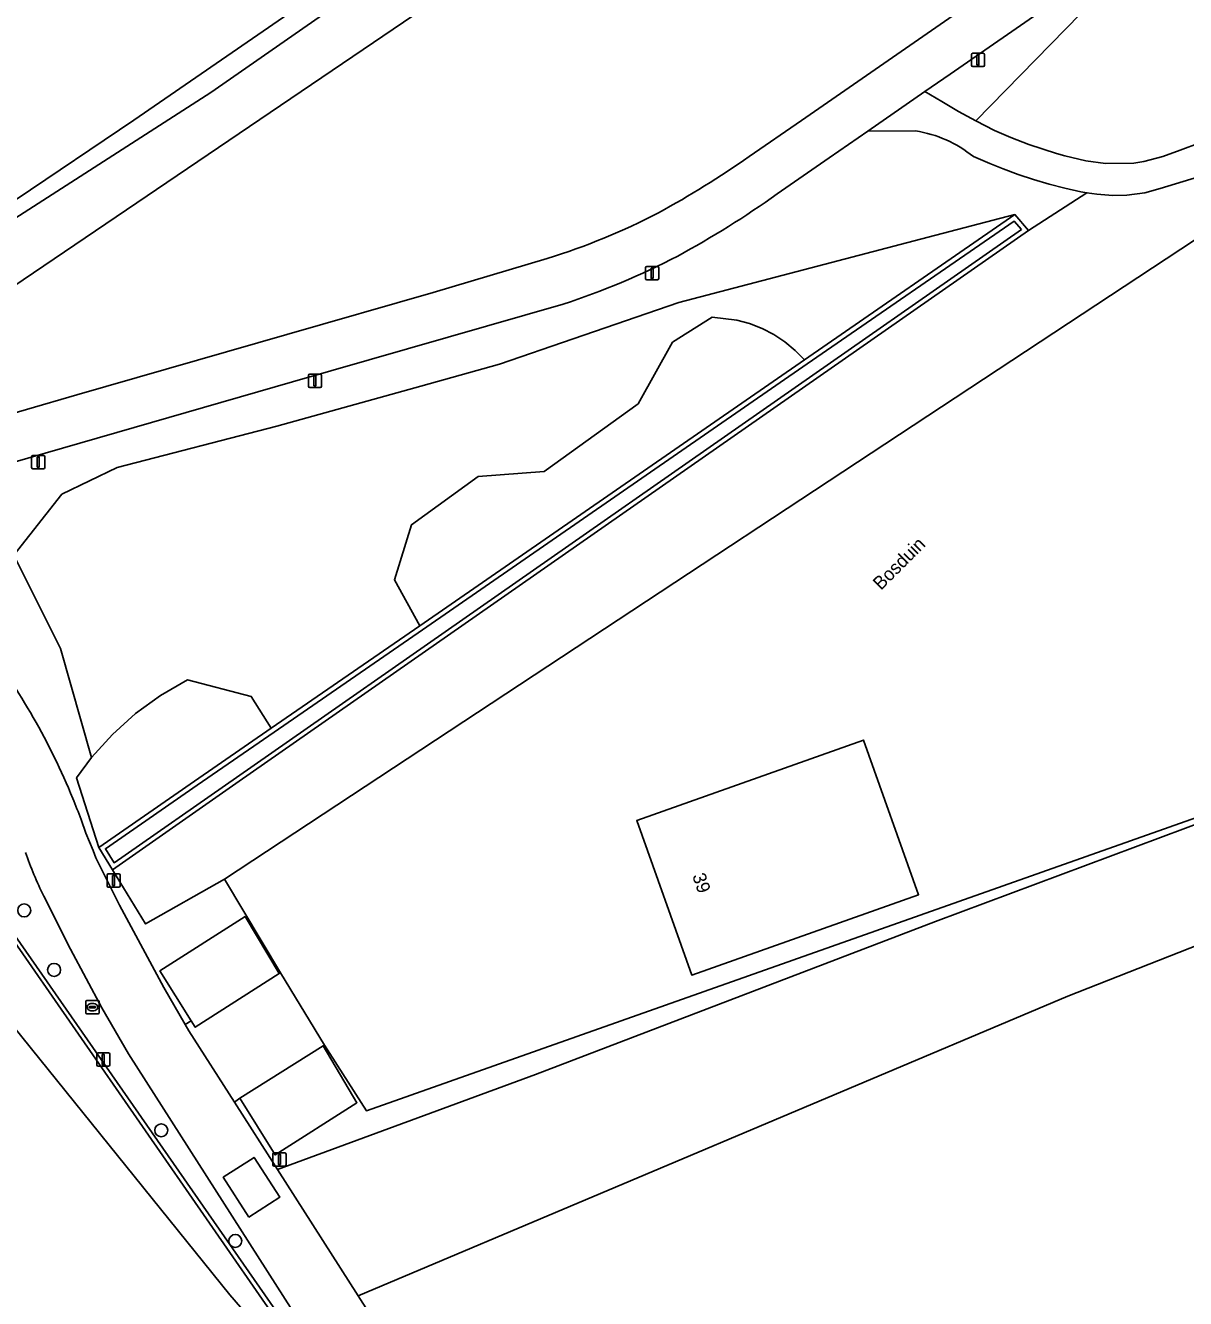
# Model space of a CAD drawing. Extents: x 156661 to 157576, y 383570 to 384425.
# Drawn here: x 157206.8 to 157294, y 383711.1 to 383806.8 of the extents above; entities that cross this region are included whole.
import ezdxf

# ---------------------------------------------------------------- set-up
doc = ezdxf.new("R2010")
doc.units = 0
for name, color, linetype in [('IMGEO_Berm_groen', 7, 'Continuous'), ('IMGEO_Boom', 7, 'Continuous'), ('IMGEO_Brandkraan', 7, 'Continuous'), ('IMGEO_Erf', 7, 'Continuous'), ('IMGEO_Fietspad_gesloten', 7, 'Continuous'), ('IMGEO_Gemengd_bos', 7, 'Continuous'), ('IMGEO_Groenvoorziening', 7, 'Continuous'), ('IMGEO_Hek', 7, 'Continuous'), ('IMGEO_Lichtmast', 7, 'Continuous'), ('IMGEO_Oever', 7, 'Continuous'), ('IMGEO_Openbare_ruimte_label', 7, 'Continuous'), ('IMGEO_Pand', 7, 'Continuous'), ('IMGEO_Pand_nummerreeks', 7, 'Continuous'), ('IMGEO_Parkeervlak_open', 7, 'Continuous'), ('IMGEO_Rijbaan_lokaal_halfverhard', 7, 'Continuous'), ('IMGEO_Rijbaan_lokaal_open', 7, 'Continuous'), ('IMGEO_Voetpad_open', 7, 'Continuous'), ('IMGEO_Waterloop', 7, 'Continuous')]:
    doc.layers.add(name, color=color, linetype=linetype)

msp = doc.modelspace()

# ---------------------------------------------------------------- linework, layer by layer
at = {"layer": 'IMGEO_Berm_groen'}
for points in [[(157198.145, 383748.914), (157205.551, 383738.59), (157225.711, 383709.501)], [(157229.992, 383702.365), (157230.186, 383702.14), (157237.396, 383693.8), (157214.571, 383729.509), (157212.581, 383732.98), (157210.224, 383737.387), (157208.207, 383741.37)]]:
    msp.add_lwpolyline(points, dxfattribs=at)
msp.add_arc((157234.02, 383754.094), 28.778, 199.14383, 206.23945, dxfattribs=at)
at = {"layer": 'IMGEO_Boom'}
for centre in [(157206.737, 383740.299), (157208.985, 383735.823), (157217.042, 383723.758), (157222.607, 383715.439)]:
    msp.add_circle(centre, 0.489, dxfattribs=at)
at = {"layer": 'IMGEO_Brandkraan'}
for p, q in [((157211.369, 383732.595), (157211.369, 383733.447)), ((157211.444, 383733.521), (157212.296, 383733.521)), ((157211.857, 383733.301), (157211.882, 383733.301)), ((157212.37, 383733.447), (157212.37, 383732.595)), ((157212.296, 383732.521), (157211.444, 383732.521)), ((157211.628, 383733.015), (157211.628, 383733.027)), ((157212.066, 383732.978), (157211.668, 383732.978)), ((157211.671, 383733.064), (157212.069, 383733.064)), ((157211.88, 383732.741), (157211.855, 383732.741)), ((157212.112, 383733.027), (157212.112, 383733.015))]:
    msp.add_line(p, q, dxfattribs=at)
for points in [[(157211.369, 383732.595), (157211.369, 383733.447)], [(157211.444, 383733.521), (157212.296, 383733.521)], [(157212.37, 383733.447), (157212.37, 383732.595)], [(157212.296, 383732.521), (157211.444, 383732.521)]]:
    msp.add_lwpolyline(points, dxfattribs=at)
for centre, radius, start, end in [((157211.446, 383733.445), 0.0765, 91.55205, 178.44795), ((157211.446, 383733.445), 0.0765, 91.55205, 178.44795), ((157212.294, 383733.445), 0.0765, 1.55205, 88.44795), ((157212.294, 383733.445), 0.0765, 1.55205, 88.44795), ((157211.446, 383732.597), 0.0765, 181.55205, 268.44795), ((157211.446, 383732.597), 0.0765, 181.55205, 268.44795), ((157211.668, 383733.024), 0.0403, 85.87752, 175.75265), ((157211.665, 383733.014), 0.0366, 178.93798, 274.71019), ((157212.069, 383733.021), 0.043, 264.86636, 352.45326), ((157212.073, 383733.026), 0.0386, 1.73085, 96.63898), ((157212.294, 383732.597), 0.0765, 271.55205, 358.44795), ((157212.294, 383732.597), 0.0765, 271.55205, 358.44795)]:
    msp.add_arc(centre, radius, start, end, dxfattribs=at)
for centre, major_axis, ratio, start_param, end_param in [((157211.856, 383733.021), (-0.387, 0.002), 0.722429, 4.712389, 7.853982), ((157211.881, 383733.021), (-0.39, 0.002), 0.717154, 1.570796, 4.712389)]:
    msp.add_ellipse(centre, major_axis=major_axis, ratio=ratio, start_param=start_param, end_param=end_param, dxfattribs=at)
at = {"layer": 'IMGEO_Erf'}
for points in [[(157324.866, 383757.87), (157348.567, 383774.345), (157335.149, 383794.067), (157314.431, 383779.837), (157312.332, 383778.396), (157311.319, 383777.7), (157300.001, 383794.175), (157221.789, 383742.655), (157226.005, 383735.606), (157229.305, 383730.173), (157232.472, 383725.228)], [(157269.845, 383753.105), (157273.982, 383741.469), (157256.92, 383735.425), (157252.784, 383747.062)]]:
    msp.add_lwpolyline(points, close=True, dxfattribs=at)
at = {"layer": 'IMGEO_Fietspad_gesloten'}
for points in [[(157287.916, 383815.454), (157265.182, 383799.676), (157261.234, 383796.979)], [(157263.339, 383794.166), (157267.26, 383796.875), (157270.156, 383798.884), (157274.455, 383801.866), (157276.351, 383803.181), (157291.807, 383813.902)], [(157246.056, 383789.316), (157237.484, 383786.756), (157226.488, 383783.6), (157210.706, 383779.058), (157195.526, 383774.656), (157193.261, 383773.95), (157190.781, 383773.162), (157194.082, 383770.561), (157197.041, 383771.438), (157198.984, 383771.987), (157226.911, 383780.04), (157247.258, 383785.88)], [(157225.711, 383709.501), (157205.551, 383738.59), (157198.145, 383748.914)], [(157194.394, 383747.91), (157198.785, 383741.887), (157205.946, 383731.565), (157222.191, 383711.388), (157229.992, 383702.365)]]:
    msp.add_lwpolyline(points, dxfattribs=at)
for centre, radius, start, end in [((157221.572, 383853.222), 68.821, 298.521, 305.19091), ((157222.466, 383851.263), 70.219, 298.40287, 305.59686), ((157231.488, 383836.75), 49.621, 287.073, 297.54271), ((157229.562, 383840.053), 56.99, 288.09, 297.48862)]:
    msp.add_arc(centre, radius, start, end, dxfattribs=at)
at = {"layer": 'IMGEO_Gemengd_bos'}
for points in [[(157321.415, 383809.74), (157325.982, 383804.89), (157336.335, 383792.758), (157352.852, 383768.572), (157329.601, 383759.614), (157324.866, 383757.87), (157303.453, 383749.98), (157275.261, 383739.464), (157245.186, 383727.961), (157225.784, 383720.815), (157231.842, 383711.326), (157232.486, 383711.598), (157285.189, 383733.84), (157326.234, 383749.98), (157358.346, 383762.608), (157368.143, 383749.98)], [(157381.207, 383680.69), (157394.48, 383676.444), (157398.069, 383669.046), (157409.138, 383666.082), (157412.12, 383680.62), (157406.857, 383688.859), (157405.202, 383690.908), (157403.342, 383692.773), (157393.317, 383702.255), (157391.63, 383719.705), (157368.143, 383749.98), (157358.346, 383762.608), (157326.234, 383749.98), (157285.189, 383733.84), (157232.486, 383711.598), (157231.842, 383711.326), (157239.82, 383698.833), (157242.24, 383695.049), (157250.444, 383682.213)]]:
    msp.add_lwpolyline(points, dxfattribs=at)
at = {"layer": 'IMGEO_Groenvoorziening'}
for points in [[(157256.426, 383855.642), (157274.334, 383862.441), (157275.122, 383862.323), (157276.244, 383861.75), (157277.981, 383860.796), (157279.723, 383859.455), (157281.416, 383861.093), (157281.585, 383860.915), (157283.573, 383858.733), (157283.744, 383858.545), (157281.661, 383856.765), (157282.167, 383855.47), (157282.539, 383854.181), (157283.065, 383852.554), (157282.825, 383851.233), (157270.898, 383836.686), (157220.767, 383801.796), (157202.144, 383789.846), (157187.988, 383785.455), (157186.935, 383784.858)], [(157175.248, 383785.492), (157183.912, 383781.17), (157187.349, 383779.354), (157191.179, 383777.222), (157291.728, 383845.369), (157293.639, 383848.286)], [(157306.327, 383830.695), (157300.098, 383825.478), (157284.532, 383814.48), (157295.297, 383823.254), (157298.672, 383826.664), (157299.693, 383827.695), (157302.195, 383830.222), (157291.728, 383845.369), (157191.179, 383777.222), (157193.836, 383775.743), (157195.526, 383774.656), (157210.706, 383779.058), (157226.488, 383783.6), (157237.484, 383786.756), (157246.056, 383789.316)], [(157261.234, 383796.979), (157265.182, 383799.676), (157287.916, 383815.454)], [(157291.807, 383813.902), (157276.351, 383803.181), (157274.455, 383801.866), (157275.718, 383801.108), (157276.988, 383800.366), (157278.272, 383799.658), (157289.535, 383811.191)], [(157289.535, 383811.191), (157278.272, 383799.658), (157279.695, 383798.946), (157280.911, 383798.409), (157282.276, 383797.882), (157284.339, 383797.211), (157284.984, 383797.031), (157286.559, 383796.66), (157288.025, 383796.45), (157290.156, 383796.474), (157290.92, 383796.604), (157292.333, 383796.993), (157293.653, 383797.464), (157295.132, 383798.016)], [(157273.754, 383798.904), (157270.156, 383798.884), (157267.26, 383796.875), (157263.339, 383794.166)], [(157283.785, 383794.896), (157282.619, 383795.24), (157281.47, 383795.622), (157280.335, 383796.042), (157279.338, 383796.445), (157278.101, 383796.981)], [(157298.075, 383796.028), (157297.044, 383795.919), (157295.639, 383795.619), (157294.458, 383795.281), (157293.292, 383794.914), (157292.131, 383794.565), (157290.982, 383794.25), (157289.625, 383794.078), (157288.594, 383794.052), (157287.384, 383794.141), (157286.634, 383794.259), (157282.252, 383791.413), (157222.91, 383750), (157213.385, 383743.353), (157215.866, 383739.273), (157221.789, 383742.655), (157300.001, 383794.175)], [(157211.011, 383747.138), (157211.37, 383746.108), (157211.913, 383744.789), (157212.135, 383744.249), (157213.251, 383741.992), (157213.898, 383740.683), (157217.227, 383734.492), (157218.844, 383731.719), (157219.293, 383732.001), (157216.945, 383735.744), (157223.342, 383739.827), (157225.904, 383735.542), (157226.005, 383735.606), (157221.789, 383742.655), (157215.866, 383739.273), (157213.385, 383743.353), (157212.359, 383745.028), (157210.675, 383750.273), (157211.805, 383751.795), (157209.462, 383759.993), (157205.957, 383767.002), (157209.577, 383771.585), (157213.737, 383773.588), (157225.729, 383776.693), (157236.559, 383779.706), (157242.466, 383781.367), (157248.017, 383783.281), (157255.943, 383786.008), (157274.71, 383790.913), (157281.219, 383792.614), (157282.252, 383791.413), (157286.634, 383794.259), (157286.172, 383794.331), (157284.983, 383794.588), (157283.785, 383794.896)], [(157247.258, 383785.88), (157226.911, 383780.04), (157198.984, 383771.987), (157200.733, 383769.984), (157197.54, 383767.411), (157198.453, 383766.449), (157199.451, 383765.365), (157200.175, 383764.578)]]:
    msp.add_lwpolyline(points, dxfattribs=at)
for points in [[(157234.569, 383765.157), (157235.85, 383769.298), (157240.862, 383772.927), (157245.842, 383773.29), (157252.891, 383778.381), (157255.49, 383783.014), (157258.454, 383784.903), (157260.315, 383784.68), (157261.279, 383784.413), (157262.209, 383784.047), (157263.096, 383783.586), (157263.929, 383783.035), (157264.701, 383782.4), (157265.402, 383781.687), (157281.219, 383792.614), (157274.71, 383790.913), (157255.943, 383786.008), (157248.017, 383783.281), (157242.466, 383781.367), (157236.559, 383779.706), (157225.729, 383776.693), (157213.737, 383773.588), (157209.577, 383771.585), (157205.957, 383767.002), (157209.462, 383759.993), (157211.805, 383751.795), (157213.369, 383753.529), (157215.105, 383755.091), (157216.995, 383756.462), (157219.018, 383757.628), (157223.811, 383756.388), (157225.314, 383753.991), (157236.473, 383761.7)], [(157264.701, 383782.4), (157263.929, 383783.035), (157263.096, 383783.586), (157262.209, 383784.047), (157261.279, 383784.413), (157260.315, 383784.68), (157258.454, 383784.903), (157255.49, 383783.014), (157252.891, 383778.381), (157245.842, 383773.29), (157240.862, 383772.927), (157235.85, 383769.298), (157234.569, 383765.157), (157236.473, 383761.7), (157265.402, 383781.687)], [(157225.314, 383753.991), (157223.811, 383756.388), (157219.018, 383757.628), (157216.995, 383756.462), (157215.105, 383755.091), (157213.369, 383753.529), (157211.805, 383751.795), (157210.675, 383750.273), (157212.359, 383745.028), (157219.546, 383750)], [(157231.747, 383725.831), (157225.605, 383721.905), (157222.954, 383726.182), (157222.557, 383725.869), (157225.784, 383720.815), (157245.186, 383727.961), (157275.261, 383739.464), (157303.453, 383749.98), (157324.866, 383757.87), (157232.472, 383725.228), (157229.305, 383730.173), (157229.21, 383730.122)]]:
    msp.add_lwpolyline(points, close=True, dxfattribs=at)
for centre, radius, start, end in [((157272.316, 383789.778), 9.238, 51.22881, 81.04448), ((157221.572, 383853.222), 68.821, 298.521, 305.19091), ((157222.466, 383851.263), 70.219, 298.40287, 305.59686), ((157231.488, 383836.75), 49.621, 287.073, 297.54271), ((157229.562, 383840.053), 56.99, 288.09, 297.48862), ((157162.319, 383728.973), 51.969, 22.33163, 37.26651), ((157157.505, 383727.081), 57.141, 20.54876, 22.25256)]:
    msp.add_arc(centre, radius, start, end, dxfattribs=at)
at = {"layer": 'IMGEO_Hek'}
for points in [[(157230.832, 383701.393), (157230.39, 383702.37), (157227.472, 383707.602), (157203.414, 383742.175), (157199.917, 383746.99), (157196.263, 383751.798), (157192.853, 383755.755), (157188.865, 383759.532)], [(157326.234, 383749.98), (157285.189, 383733.84), (157232.486, 383711.598)], [(157232.486, 383711.598), (157231.842, 383711.326)]]:
    msp.add_lwpolyline(points, dxfattribs=at)
at = {"layer": 'IMGEO_Lichtmast'}
for p, q in [((157277.949, 383803.841), (157277.949, 383804.641)), ((157277.949, 383804.641), (157277.949, 383803.841)), ((157278.049, 383804.741), (157278.839, 383804.741)), ((157278.839, 383804.741), (157278.049, 383804.741)), ((157278.939, 383804.641), (157278.939, 383803.841)), ((157278.939, 383803.841), (157278.939, 383804.641)), ((157278.839, 383803.741), (157278.049, 383803.741)), ((157278.049, 383803.741), (157278.839, 383803.741)), ((157253.452, 383787.804), (157253.452, 383788.604)), ((157253.452, 383788.604), (157253.452, 383787.804)), ((157253.552, 383788.704), (157254.342, 383788.704)), ((157254.342, 383788.704), (157253.552, 383788.704)), ((157254.442, 383788.604), (157254.442, 383787.804)), ((157254.442, 383787.804), (157254.442, 383788.604)), ((157254.342, 383787.704), (157253.552, 383787.704)), ((157253.552, 383787.704), (157254.342, 383787.704)), ((157228.104, 383779.715), (157228.104, 383780.515)), ((157228.104, 383780.515), (157228.104, 383779.715)), ((157228.204, 383780.615), (157228.994, 383780.615)), ((157228.994, 383780.615), (157228.204, 383780.615)), ((157229.094, 383780.515), (157229.094, 383779.715)), ((157229.094, 383779.715), (157229.094, 383780.515)), ((157228.994, 383779.615), (157228.204, 383779.615)), ((157228.204, 383779.615), (157228.994, 383779.615)), ((157207.397, 383774.502), (157208.187, 383774.502)), ((157208.187, 383774.502), (157207.397, 383774.502)), ((157207.297, 383773.602), (157207.297, 383774.402)), ((157207.297, 383774.402), (157207.297, 383773.602)), ((157208.187, 383773.502), (157207.397, 383773.502)), ((157207.397, 383773.502), (157208.187, 383773.502)), ((157208.287, 383774.402), (157208.287, 383773.602)), ((157208.287, 383773.602), (157208.287, 383774.402)), ((157212.963, 383742.145), (157212.963, 383742.945)), ((157212.963, 383742.945), (157212.963, 383742.145)), ((157213.063, 383743.045), (157213.853, 383743.045)), ((157213.853, 383743.045), (157213.063, 383743.045)), ((157213.953, 383742.945), (157213.953, 383742.145)), ((157213.953, 383742.145), (157213.953, 383742.945)), ((157213.853, 383742.045), (157213.063, 383742.045)), ((157213.063, 383742.045), (157213.853, 383742.045)), ((157212.19, 383728.682), (157212.19, 383729.482)), ((157212.19, 383729.482), (157212.19, 383728.682)), ((157212.29, 383729.582), (157213.08, 383729.582)), ((157213.08, 383729.582), (157212.29, 383729.582)), ((157213.18, 383729.482), (157213.18, 383728.682)), ((157213.18, 383728.682), (157213.18, 383729.482)), ((157213.08, 383728.582), (157212.29, 383728.582)), ((157212.29, 383728.582), (157213.08, 383728.582)), ((157225.432, 383721.166), (157225.432, 383721.966)), ((157225.432, 383721.966), (157225.432, 383721.166)), ((157225.532, 383722.066), (157226.322, 383722.066)), ((157226.322, 383722.066), (157225.532, 383722.066)), ((157226.422, 383721.966), (157226.422, 383721.166)), ((157226.422, 383721.166), (157226.422, 383721.966)), ((157226.322, 383721.066), (157225.532, 383721.066)), ((157225.532, 383721.066), (157226.322, 383721.066))]:
    msp.add_line(p, q, dxfattribs=at)
for points in [[(157278.369, 383804.616), (157278.519, 383804.616), (157278.519, 383803.866), (157278.369, 383803.866), (157278.369, 383804.616)], [(157253.872, 383788.579), (157254.022, 383788.579), (157254.022, 383787.829), (157253.872, 383787.829), (157253.872, 383788.579)], [(157228.524, 383780.49), (157228.674, 383780.49), (157228.674, 383779.74), (157228.524, 383779.74), (157228.524, 383780.49)], [(157207.717, 383774.377), (157207.867, 383774.377), (157207.867, 383773.627), (157207.717, 383773.627), (157207.717, 383774.377)], [(157213.383, 383742.92), (157213.533, 383742.92), (157213.533, 383742.17), (157213.383, 383742.17), (157213.383, 383742.92)], [(157212.61, 383729.457), (157212.76, 383729.457), (157212.76, 383728.707), (157212.61, 383728.707), (157212.61, 383729.457)], [(157225.852, 383721.941), (157226.002, 383721.941), (157226.002, 383721.191), (157225.852, 383721.191), (157225.852, 383721.941)]]:
    msp.add_lwpolyline(points, dxfattribs=at)
for centre, start, end in [((157278.049, 383804.641), 90, 180), ((157278.049, 383804.641), 90, 180), ((157278.839, 383804.641), 0, 90), ((157278.839, 383804.641), 360, 90), ((157278.049, 383803.841), 180, 270), ((157278.049, 383803.841), 180, 270), ((157278.839, 383803.841), 270, 0), ((157278.839, 383803.841), 270, 0), ((157253.552, 383788.604), 90, 180), ((157253.552, 383788.604), 90, 180), ((157254.342, 383788.604), 0, 90), ((157254.342, 383788.604), 360, 90), ((157253.552, 383787.804), 180, 270), ((157253.552, 383787.804), 180, 270), ((157254.342, 383787.804), 270, 0), ((157254.342, 383787.804), 270, 0), ((157228.204, 383780.515), 90, 180), ((157228.204, 383780.515), 90, 180), ((157228.994, 383780.515), 0, 90), ((157228.994, 383780.515), 360, 90), ((157228.204, 383779.715), 180, 270), ((157228.204, 383779.715), 180, 270), ((157228.994, 383779.715), 270, 0), ((157228.994, 383779.715), 270, 0), ((157207.397, 383774.402), 90, 180), ((157207.397, 383774.402), 90, 180), ((157208.187, 383774.402), 0, 90), ((157208.187, 383774.402), 360, 90), ((157207.397, 383773.602), 180, 270), ((157207.397, 383773.602), 180, 270), ((157208.187, 383773.602), 270, 0), ((157208.187, 383773.602), 270, 0), ((157213.063, 383742.945), 90, 180), ((157213.063, 383742.945), 90, 180), ((157213.853, 383742.945), 0, 90), ((157213.853, 383742.945), 360, 90), ((157213.063, 383742.145), 180, 270), ((157213.063, 383742.145), 180, 270), ((157213.853, 383742.145), 270, 0), ((157213.853, 383742.145), 270, 0), ((157212.29, 383729.482), 90, 180), ((157212.29, 383729.482), 90, 180), ((157213.08, 383729.482), 0, 90), ((157213.08, 383729.482), 360, 90), ((157212.29, 383728.682), 180, 270), ((157212.29, 383728.682), 180, 270), ((157213.08, 383728.682), 270, 0), ((157213.08, 383728.682), 270, 0), ((157225.532, 383721.966), 90, 180), ((157225.532, 383721.966), 90, 180), ((157226.322, 383721.966), 0, 90), ((157226.322, 383721.966), 360, 90), ((157225.532, 383721.166), 180, 270), ((157225.532, 383721.166), 180, 270), ((157226.322, 383721.166), 270, 0), ((157226.322, 383721.166), 270, 0)]:
    msp.add_arc(centre, 0.1, start, end, dxfattribs=at)
at = {"layer": 'IMGEO_Oever'}
for points in [[(157269.71, 383837.399), (157214.991, 383799.721), (157206.144, 383793.738), (157198.524, 383790.396), (157185.168, 383787.269), (157185.136, 383787.262), (157185.48, 383785.456), (157185.171, 383785.288), (157184.01, 383784.932), (157182.901, 383784.848), (157181.835, 383784.863), (157180.994, 383785.492), (157177.788, 383788.045), (157177.346, 383788.252), (157177.198, 383788.841), (157177.137, 383789.92), (157178.474, 383793.156), (157180.576, 383792.21), (157182.135, 383794.809), (157189.081, 383807.099)], [(157186.935, 383784.858), (157187.988, 383785.455), (157202.144, 383789.846), (157220.767, 383801.796), (157270.898, 383836.686)]]:
    msp.add_lwpolyline(points, dxfattribs=at)
for points in [[(157282.252, 383791.413), (157281.219, 383792.614), (157265.402, 383781.687), (157236.473, 383761.7), (157225.314, 383753.991), (157219.546, 383750), (157212.359, 383745.028), (157213.385, 383743.353), (157222.91, 383750)], [(157281.713, 383791.481), (157222.702, 383750.298), (157213.494, 383743.873), (157212.849, 383744.925), (157219.753, 383749.701), (157225.521, 383753.692), (157236.68, 383761.401), (157265.609, 383781.388), (157281.157, 383792.128)]]:
    msp.add_lwpolyline(points, close=True, dxfattribs=at)
at = {"layer": 'IMGEO_Pand'}
msp.add_lwpolyline([(157256.92, 383735.425), (157273.982, 383741.469), (157269.845, 383753.105), (157252.784, 383747.062)], close=True, dxfattribs=at)
at = {"layer": 'IMGEO_Parkeervlak_open'}
for points in [[(157223.342, 383739.827), (157216.945, 383735.744), (157219.293, 383732.001), (157219.6, 383731.512), (157225.904, 383735.542)], [(157229.21, 383730.122), (157222.954, 383726.182), (157225.605, 383721.905), (157231.747, 383725.831)]]:
    msp.add_lwpolyline(points, close=True, dxfattribs=at)
at = {"layer": 'IMGEO_Rijbaan_lokaal_halfverhard'}
for points in [[(157295.132, 383798.016), (157293.653, 383797.464), (157292.333, 383796.993), (157290.92, 383796.604), (157290.156, 383796.474), (157288.025, 383796.45), (157286.559, 383796.66), (157284.984, 383797.031), (157284.339, 383797.211), (157282.276, 383797.882), (157280.911, 383798.409), (157279.695, 383798.946), (157278.272, 383799.658), (157276.988, 383800.366), (157275.718, 383801.108), (157274.455, 383801.866), (157270.156, 383798.884), (157273.754, 383798.904)], [(157278.101, 383796.981), (157279.338, 383796.445), (157280.335, 383796.042), (157281.47, 383795.622), (157282.619, 383795.24), (157283.785, 383794.896), (157284.983, 383794.588), (157286.172, 383794.331), (157286.634, 383794.259), (157287.384, 383794.141), (157288.594, 383794.052), (157289.625, 383794.078), (157290.982, 383794.25), (157292.131, 383794.565), (157293.292, 383794.914), (157294.458, 383795.281)]]:
    msp.add_lwpolyline(points, dxfattribs=at)
msp.add_arc((157272.316, 383789.778), 9.238, 51.22881, 81.04448, dxfattribs=at)
at = {"layer": 'IMGEO_Rijbaan_lokaal_open'}
for points in [[(157250.444, 383682.213), (157242.24, 383695.049), (157239.82, 383698.833), (157231.842, 383711.326), (157225.784, 383720.815), (157222.557, 383725.869), (157219.123, 383731.24), (157218.844, 383731.719), (157217.227, 383734.492), (157213.898, 383740.683), (157213.251, 383741.992), (157212.135, 383744.249), (157211.913, 383744.789), (157211.37, 383746.108), (157211.011, 383747.138)], [(157208.207, 383741.37), (157210.224, 383737.387), (157212.581, 383732.98), (157214.571, 383729.509), (157237.396, 383693.8), (157257.379, 383670.684), (157284.92, 383639.23)]]:
    msp.add_lwpolyline(points, dxfattribs=at)
for points in [[(157223.627, 383717.231), (157225.947, 383718.724), (157224.016, 383721.724), (157221.697, 383720.23)], [(157223.627, 383717.231), (157221.697, 383720.23), (157224.016, 383721.724), (157225.947, 383718.724)]]:
    msp.add_lwpolyline(points, close=True, dxfattribs=at)
for centre, radius, start, end in [((157162.319, 383728.973), 51.969, 22.33163, 37.26651), ((157157.505, 383727.081), 57.141, 20.54876, 22.25256), ((157234.02, 383754.094), 28.778, 199.14383, 206.23945)]:
    msp.add_arc(centre, radius, start, end, dxfattribs=at)
at = {"layer": 'IMGEO_Voetpad_open'}
msp.add_lwpolyline([(157226.005, 383735.606), (157225.904, 383735.542), (157219.6, 383731.512), (157219.293, 383732.001), (157218.844, 383731.719), (157219.123, 383731.24), (157222.557, 383725.869), (157222.954, 383726.182), (157229.21, 383730.122), (157229.305, 383730.173)], close=True, dxfattribs=at)
at = {"layer": 'IMGEO_Waterloop'}
msp.add_lwpolyline([(157189.081, 383807.099), (157182.135, 383794.809), (157180.576, 383792.21), (157178.518, 383788.78), (157178.602, 383788.721), (157178.236, 383788.199), (157179.455, 383787.229), (157179.809, 383787.699), (157179.927, 383787.605), (157179.574, 383787.139), (157179.725, 383787.014), (157180.092, 383787.474), (157180.21, 383787.381), (157179.842, 383786.921), (157180.998, 383786.001), (157181.404, 383786.517), (157181.522, 383786.424), (157185.136, 383787.262), (157185.168, 383787.269), (157198.524, 383790.396), (157206.144, 383793.738), (157214.991, 383799.721), (157269.71, 383837.399)], dxfattribs=at)
msp.add_lwpolyline([(157281.713, 383791.481), (157281.157, 383792.128), (157265.609, 383781.388), (157236.68, 383761.401), (157225.521, 383753.692), (157219.753, 383749.701), (157212.849, 383744.925), (157213.494, 383743.873), (157222.702, 383750.298)], close=True, dxfattribs=at)

# ---------------------------------------------------------------- texts
at = {"layer": 'IMGEO_Openbare_ruimte_label'}
msp.add_text('Bosduin', height=1, rotation=45, dxfattribs=at).set_placement((157271.151, 383764.325))
at = {"layer": 'IMGEO_Pand_nummerreeks'}
msp.add_text('39', height=1, rotation=289.29005, dxfattribs=at).set_placement((157256.948, 383742.9))

doc.saveas('drawing.dxf')
